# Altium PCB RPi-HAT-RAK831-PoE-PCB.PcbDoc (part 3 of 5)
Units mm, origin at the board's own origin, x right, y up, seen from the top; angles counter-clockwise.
Board outline 65 x 56 mm, 2 copper layers (Top Layer, Bottom Layer); 9 components, 14 nets, 9110 pads, 249 vias.
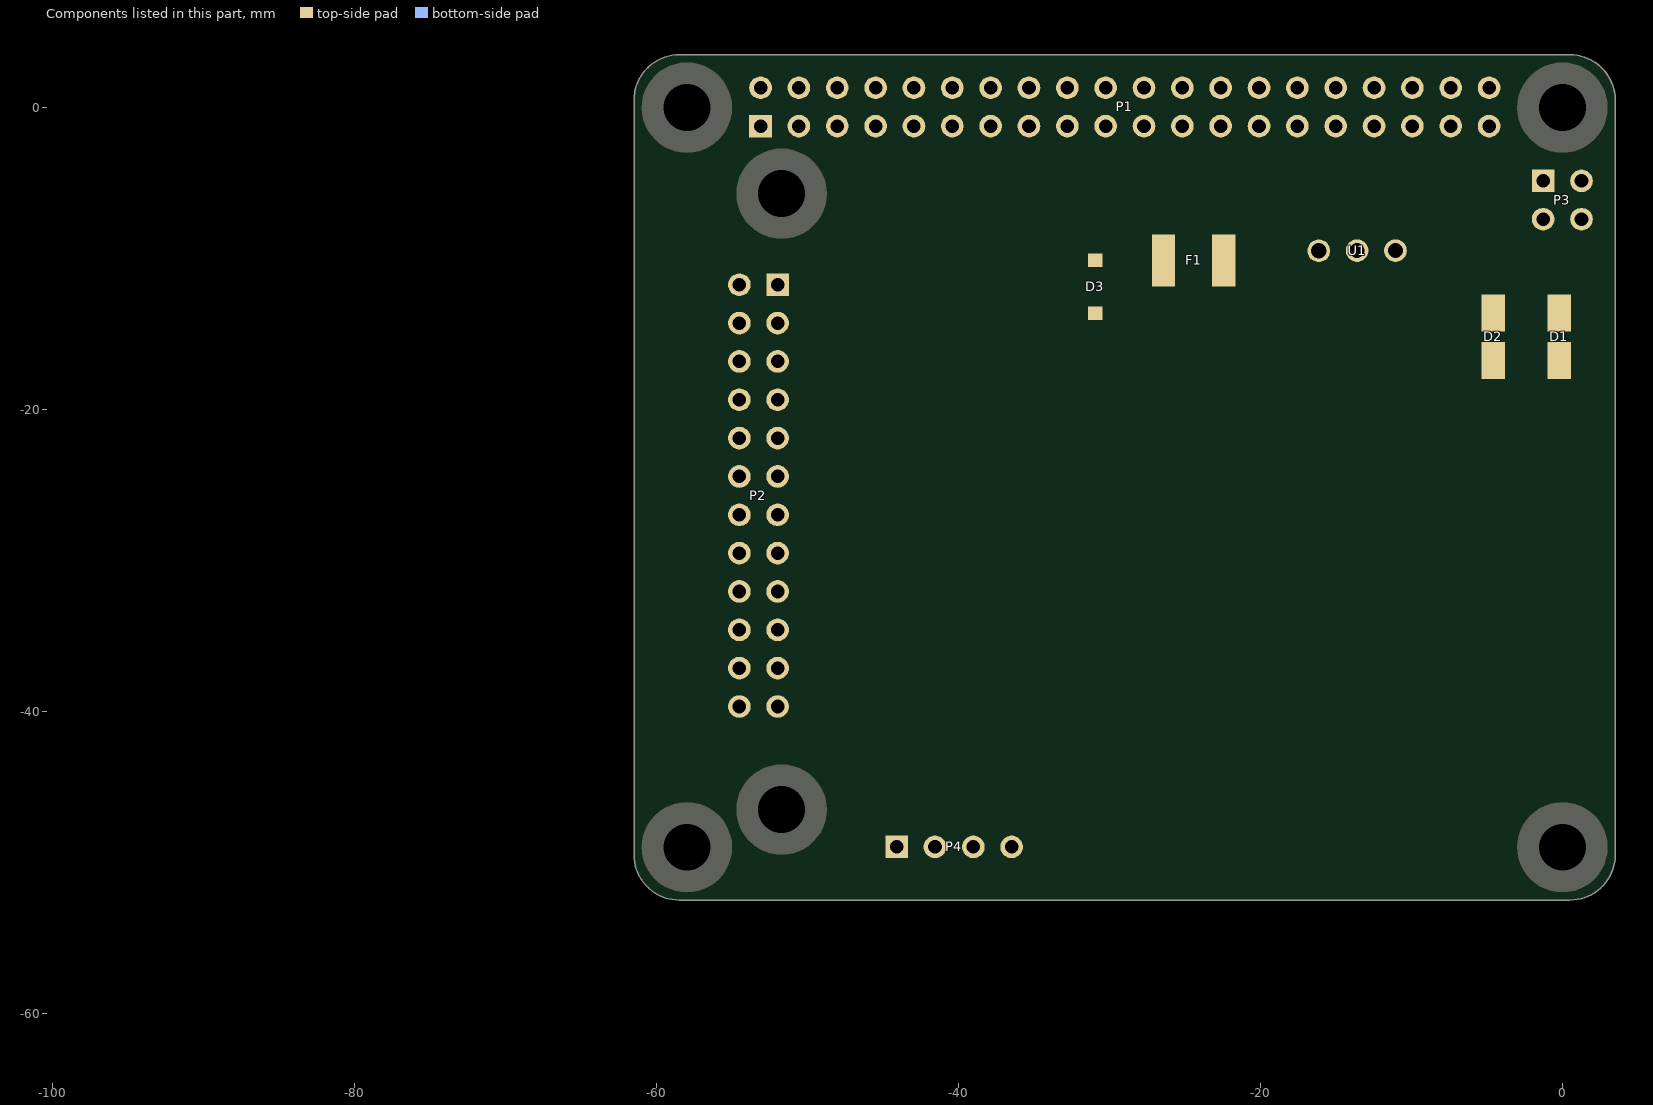
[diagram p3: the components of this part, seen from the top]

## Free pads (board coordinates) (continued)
  round 0.025 on Bottom Overlay: 1(-16.645,-44.787) 1(-16.645,-44.761) 1(-16.645,-44.736) 1(-16.645,-44.71) 1(-16.645,-44.685) 1(-16.645,-44.66) 1(-16.645,-44.634) 1(-16.645,-44.609) 1(-16.645,-44.583) 1(-16.645,-44.558) 1(-16.645,-44.533) 1(-16.645,-44.507) 1(-16.645,-44.482) 1(-16.645,-44.456) 1(-16.62,-45.193) 1(-16.594,-42.043) 1(-16.569,-45.218) 1(-16.493,-45.244) 1(-16.493,-42.729) 1(-16.442,-45.955) 1(-16.34,-45.269) 1(-16.061,-42.729) 1(-15.959,-45.269) 1(-15.959,-42.043) 1(-15.909,-42.755) 1(-15.883,-44.431) 1(-15.883,-44.406) 1(-15.883,-44.38) 1(-15.883,-44.355) 1(-15.883,-44.329) 1(-15.883,-44.304) 1(-15.883,-44.279) 1(-15.883,-44.253) 1(-15.883,-44.228) 1(-15.883,-44.202) 1(-15.883,-44.177) 1(-15.883,-44.152) 1(-15.883,-44.126) 1(-15.883,-44.101) 1(-15.883,-44.075) 1(-15.883,-44.05) 1(-15.883,-44.025) 1(-15.883,-43.999) 1(-15.883,-43.974) 1(-15.883,-43.948) 1(-15.883,-43.923) 1(-15.883,-43.898) 1(-15.883,-43.872) 1(-15.883,-43.847) 1(-15.883,-43.821) 1(-15.883,-43.796) 1(-15.883,-43.771) 1(-15.832,-45.244) 1(-15.832,-42.78) 1(-15.807,-45.955) 1(-15.756,-45.218) 1(-15.756,-42.805) 1(-15.756,-42.069) 1(-15.705,-42.831) 1(-15.68,-45.193) 1(-15.655,-42.856) 1(-15.629,-45.93) 1(-15.629,-45.168) 1(-15.629,-42.094) 1(-15.604,-42.882) 1(-15.578,-45.142) 1(-15.553,-42.907) 1(-15.528,-45.117) 1(-15.528,-42.932) 1(-15.528,-42.12) 1(-15.502,-45.904) 1(-15.477,-45.091) 1(-15.477,-42.958) 1(-15.451,-45.066) 1(-15.451,-42.983) 1(-15.451,-42.145) 1(-15.426,-45.041) 1(-15.426,-43.009) 1(-15.401,-45.879) 1(-15.401,-45.015) 1(-15.401,-43.034) 1(-15.375,-44.99) 1(-15.375,-43.059) 1(-15.375,-42.17) 1(-15.35,-44.964) 1(-15.35,-43.085) 1(-15.324,-44.939) 1(-15.324,-43.11) 1(-15.299,-45.853) 1(-15.299,-44.914) 1(-15.299,-43.136) 1(-15.299,-42.196) 1(-15.274,-44.888) 1(-15.274,-43.161) 1(-15.248,-45.828) 1(-15.248,-44.863) 1(-15.248,-43.212) 1(-15.248,-43.186) 1(-15.248,-42.221) 1(-15.223,-44.837) 1(-15.223,-44.812) 1(-15.223,-43.237) 1(-15.197,-44.787) 1(-15.197,-43.288) 1(-15.197,-43.263) 1(-15.197,-42.247) 1(-15.172,-45.803) 1(-15.172,-44.761) 1(-15.172,-44.736) 1(-15.172,-43.339) 1(-15.172,-43.313) 1(-15.147,-44.71) 1(-15.147,-44.685) 1(-15.147,-43.39) 1(-15.147,-43.364) 1(-15.147,-42.272) 1(-15.121,-45.777) 1(-15.121,-44.66) 1(-15.121,-44.634) 1(-15.121,-44.609) 1(-15.121,-43.44) 1(-15.121,-43.415) 1(-15.096,-44.583) 1(-15.096,-44.558) 1(-15.096,-43.517) 1(-15.096,-43.491) 1(-15.096,-43.466) 1(-15.096,-42.297) 1(-15.07,-45.752) 1(-15.07,-44.533) 1(-15.07,-44.507) 1(-15.07,-44.482) 1(-15.07,-44.456) 1(-15.07,-43.593) 1(-15.07,-43.567) 1(-15.07,-43.542) 1(-15.045,-44.431) 1(-15.045,-44.406) 1(-15.045,-44.38) 1(-15.045,-44.355) 1(-15.045,-44.329) 1(-15.045,-43.72) 1(-15.045,-43.694) 1(-15.045,-43.669) 1(-15.045,-43.644) 1(-15.045,-43.618) 1(-15.045,-42.323) 1(-15.02,-45.726) 1(-15.02,-44.304) 1(-15.02,-44.279) 1(-15.02,-44.253) 1(-15.02,-44.228) 1(-15.02,-44.202) 1(-15.02,-44.177) 1(-15.02,-44.152) 1(-15.02,-44.126) 1(-15.02,-44.101) 1(-15.02,-44.075) 1(-15.02,-44.05) 1(-15.02,-44.025) 1(-15.02,-43.999) 1(-15.02,-43.974) 1(-15.02,-43.948) 1(-15.02,-43.923) 1(-15.02,-43.898) 1(-15.02,-43.872) 1(-15.02,-43.847) 1(-15.02,-43.821) 1(-15.02,-43.796) 1(-15.02,-43.771) 1(-15.02,-43.745) 1(-15.02,-42.348) 1(-14.969,-45.701) 1(-14.969,-42.374) 1(-14.943,-42.399) 1(-14.918,-45.676) 1(-14.893,-45.65) 1(-14.893,-42.424) 1(-14.867,-42.45) 1(-14.842,-45.625) 1(-14.842,-42.475) 1(-14.816,-45.599) 1(-14.791,-42.501) 1(-14.766,-45.574) 1(-14.766,-42.526) 1(-14.74,-45.549) 1(-14.74,-42.551) 1(-14.715,-45.523) 1(-14.715,-42.577) 1(-14.689,-45.498) 1(-14.689,-42.602) 1(-14.664,-45.472) 1(-14.664,-42.628) 1(-14.639,-45.447) 1(-14.639,-42.653) 1(-14.613,-45.422) 1(-14.613,-42.678) 1(-14.588,-45.396) 1(-14.588,-42.704) 1(-14.562,-45.371) 1(-14.562,-42.729) 1(-14.537,-45.345) 1(-14.537,-42.78) 1(-14.537,-42.755) 1(-14.512,-45.32) 1(-14.512,-42.805) 1(-14.486,-45.295) 1(-14.486,-45.269) 1(-14.486,-42.831) 1(-14.461,-45.244) 1(-14.461,-42.882) 1(-14.461,-42.856) 1(-14.435,-45.218) 1(-14.435,-42.907) 1(-14.41,-45.193) 1(-14.41,-45.168) 1(-14.41,-42.958) 1(-14.41,-42.932) 1(-14.385,-45.142) 1(-14.385,-45.117) 1(-14.385,-42.983) 1(-14.359,-45.091) 1(-14.359,-43.034) 1(-14.359,-43.009) 1(-14.334,-45.066) 1(-14.334,-45.041) 1(-14.334,-43.085) 1(-14.334,-43.059) 1(-14.308,-45.015) 1(-14.308,-44.99) 1(-14.308,-43.136) 1(-14.308,-43.11) 1(-14.283,-44.964) 1(-14.283,-44.939) 1(-14.283,-43.186) 1(-14.283,-43.161) 1(-14.258,-44.914) 1(-14.258,-44.888) 1(-14.258,-44.863) 1(-14.258,-43.263) 1(-14.258,-43.237) 1(-14.258,-43.212) 1(-14.232,-44.837) 1(-14.232,-44.812) 1(-14.232,-44.787) 1(-14.232,-43.339) 1(-14.232,-43.313) 1(-14.232,-43.288) 1(-14.207,-44.761) 1(-14.207,-44.736) 1(-14.207,-44.71) 1(-14.207,-43.415) 1(-14.207,-43.39) 1(-14.207,-43.364) 1(-14.181,-44.685) 1(-14.181,-44.66) 1(-14.181,-44.634) 1(-14.181,-44.609) 1(-14.181,-43.517) 1(-14.181,-43.491) 1(-14.181,-43.466) 1(-14.181,-43.44) 1(-14.156,-44.583) 1(-14.156,-44.558) 1(-14.156,-44.533) 1(-14.156,-44.507) 1(-14.156,-44.482) 1(-14.156,-43.644) 1(-14.156,-43.618) 1(-14.156,-43.593) 1(-14.156,-43.567) 1(-14.156,-43.542) 1(-14.131,-44.456) 1(-14.131,-44.431) 1(-14.131,-44.406) 1(-14.131,-44.38) 1(-14.131,-44.355) 1(-14.131,-44.329) 1(-14.131,-44.304) 1(-14.131,-44.279) 1(-14.131,-44.253) 1(-14.131,-43.872) 1(-14.131,-43.847) 1(-14.131,-43.821) 1(-14.131,-43.796) 1(-14.131,-43.771) 1(-14.131,-43.745) 1(-14.131,-43.72) 1(-14.131,-43.694) 1(-14.131,-43.669) 1(-14.105,-44.228) 1(-14.105,-44.202) 1(-14.105,-44.177) 1(-14.105,-44.152) 1(-14.105,-44.126) 1(-14.105,-44.101) 1(-14.105,-44.075) 1(-14.105,-44.05) 1(-14.105,-44.025) 1(-14.105,-43.999) 1(-14.105,-43.974) 1(-14.105,-43.948) 1(-14.105,-43.923) 1(-14.105,-43.898) 1(-13.271,-43.362) 1(-13.271,-43.337) 1(-13.271,-43.311) 1(-13.271,-43.286) 1(-13.271,-43.26) 1(-13.271,-43.235) 1(-13.271,-43.21) 1(-13.271,-43.184) 1(-13.271,-43.159) 1(-13.271,-43.133) 1(-13.271,-43.108) 1(-13.271,-43.083) 1(-13.271,-43.057) 1(-13.22,-43.362) 1(-13.22,-43.337) 1(-13.22,-43.311) 1(-13.22,-43.286) 1(-13.22,-43.26) 1(-13.22,-43.235) 1(-13.22,-43.21) 1(-13.22,-43.057) 1(-13.195,-43.286) 1(-13.195,-43.26) 1(-13.195,-43.235) 1(-13.195,-43.21) 1(-13.195,-43.133) 1(-13.195,-43.108) 1(-13.195,-43.083) 1(-13.17,-43.337) 1(-13.17,-43.311) 1(-13.17,-43.184) 1(-13.17,-43.159) 1(-13.144,-43.362) 1(-13.144,-43.26) 1(-13.144,-43.235) 1(-13.144,-43.21) 1(-13.119,-43.26) 1(-13.119,-43.235) 1(-13.093,-43.362) 1(-13.093,-43.337) 1(-13.093,-43.21) 1(-13.093,-43.184) 1(-13.068,-43.311) 1(-13.068,-43.286) 1(-13.068,-43.26) 1(-13.068,-43.159) 1(-13.068,-43.133) 1(-13.068,-43.108) 1(-13.043,-43.235) 1(-13.043,-43.21) 1(-13.043,-43.184) 1(-13.043,-43.083) 1(-13.043,-43.057) 1(-13.017,-43.362) 1(-13.017,-43.337) 1(-13.017,-43.311) 1(-13.017,-43.286) 1(-13.017,-43.26) 1(-13.017,-43.235) 1(-13.017,-43.21) 1(-13.017,-43.184) 1(-12.966,-43.362) 1(-12.966,-43.337) 1(-12.966,-43.311) 1(-12.966,-43.286) 1(-12.966,-43.26) 1(-12.966,-43.235) 1(-12.966,-43.21) 1(-12.966,-43.184) 1(-12.966,-43.159) 1(-12.966,-43.133) 1(-12.966,-43.108) 1(-12.966,-43.083) 1(-12.966,-43.057) 1(-12.941,-43.083) 1(-12.941,-43.057) 1(-12.839,-43.362) 1(-12.839,-43.337) 1(-12.839,-43.311) 1(-12.839,-43.286) 1(-12.839,-43.26) 1(-12.839,-43.235) 1(-12.839,-43.21) 1(-12.839,-43.184) 1(-12.839,-43.159) 1(-12.839,-43.133) 1(-12.839,-43.108) 1(-12.763,-44.886) 1(-12.763,-43.362) 1(-12.763,-43.337) 1(-12.763,-43.311) 1(-12.763,-43.286) 1(-12.763,-43.26) 1(-12.763,-43.235) 1(-12.763,-43.21) 1(-12.763,-43.184) 1(-12.763,-43.159) 1(-12.763,-43.133) 1(-12.763,-43.108) 1(-12.738,-44.861) 1(-12.738,-44.835) 1(-12.738,-44.81) 1(-12.738,-44.784) 1(-12.738,-44.759) 1(-12.738,-44.734) 1(-12.738,-44.708) 1(-12.712,-44.683) 1(-12.712,-44.657) 1(-12.712,-44.632) 1(-12.712,-44.607) 1(-12.712,-44.581) 1(-12.712,-44.556) 1(-12.712,-44.53) 1(-12.712,-44.505) 1(-12.712,-44.48) 1(-12.712,-44.454) 1(-12.712,-44.429) 1(-12.712,-44.403) 1(-12.712,-44.378) 1(-12.712,-44.353) 1(-12.712,-44.327) 1(-12.712,-44.302) 1(-12.712,-44.276) 1(-12.712,-44.251) 1(-12.712,-44.226) 1(-12.712,-44.2) 1(-12.712,-44.175) 1(-12.712,-44.149) 1(-12.712,-44.124) 1(-12.712,-44.099) 1(-12.712,-44.073) 1(-12.712,-44.048) 1(-12.712,-44.022) 1(-12.712,-43.997) 1(-12.712,-43.972) 1(-12.712,-43.946) 1(-12.712,-43.921) 1(-12.712,-43.895) 1(-12.712,-43.87) 1(-12.712,-43.845) 1(-12.712,-43.819) 1(-12.712,-43.794) 1(-12.712,-43.768) 1(-12.712,-43.743) 1(-12.712,-43.718) 1(-12.712,-43.692) 1(-12.712,-43.667) 1(-12.712,-43.641) 1(-12.712,-43.616) 1(-12.712,-43.591) 1(-12.712,-43.565) 1(-12.712,-43.54) 1(-12.712,-43.514) 1(-12.712,-43.489) 1(-12.712,-43.464) 1(-12.687,-43.438) 1(-12.687,-43.413) 1(-12.687,-43.387) 1(-12.687,-43.083) 1(-12.687,-43.057) 1(-12.662,-43.362) 1(-12.662,-43.337) 1(-12.636,-43.311) 1(-12.636,-43.286) 1(-12.611,-43.26) 1(-12.585,-43.235) 1(-12.535,-43.21) 1(-12.509,-43.184) 1(-12.458,-43.159) 1(-12.382,-43.133) 1(-12.306,-43.108) 1(-12.255,-44.886) 1(-12.255,-44.861) 1(-12.255,-44.835) 1(-12.255,-44.81) 1(-12.23,-44.784) 1(-12.23,-44.759) 1(-12.204,-44.759) 1(-12.204,-44.251) 1(-12.204,-44.226) 1(-12.204,-44.2) 1(-12.204,-44.175) 1(-12.204,-44.149) 1(-12.204,-44.124) 1(-12.204,-44.099) 1(-12.204,-44.073) 1(-12.204,-43.718) 1(-12.204,-43.692) 1(-12.204,-43.667) 1(-12.204,-43.641) 1(-12.204,-43.616) 1(-12.204,-43.591) 1(-12.204,-43.565) 1(-12.204,-43.54) 1(-12.179,-44.784) 1(-12.179,-44.327) 1(-12.179,-44.302) 1(-12.179,-44.276) 1(-12.179,-43.514) 1(-12.179,-43.489) 1(-12.179,-43.083) 1(-12.154,-44.81) 1(-12.154,-44.403) 1(-12.154,-44.378) 1(-12.154,-44.353) 1(-12.154,-43.464) 1(-12.128,-44.835) 1(-12.128,-44.429) 1(-12.128,-44.073) 1(-12.103,-44.454) 1(-12.103,-43.743) 1(-12.103,-43.438) 1(-12.077,-44.861) 1(-12.077,-44.48) 1(-12.052,-44.505) 1(-12.027,-44.886) 1(-12.027,-44.099) 1(-12.027,-43.413) 1(-11.976,-44.53) 1(-11.95,-44.911) 1(-11.925,-44.124) 1(-11.9,-43.768) 1(-11.9,-43.413) 1(-11.849,-44.937) 1(-11.849,-44.149) 1(-11.823,-43.438) 1(-11.798,-43.464) 1(-11.773,-44.175) 1(-11.773,-43.794) 1(-11.747,-43.514) 1(-11.747,-43.489) 1(-11.722,-44.53) 1(-11.722,-44.2) 1(-11.722,-43.591) 1(-11.722,-43.565) 1(-11.722,-43.54) 1(-11.722,-43.083) 1(-11.696,-44.226) 1(-11.696,-43.819) 1(-11.696,-43.641) 1(-11.696,-43.616) 1(-11.671,-44.505) 1(-11.671,-44.48) 1(-11.671,-44.251) 1(-11.646,-44.454) 1(-11.646,-44.302) 1(-11.646,-44.276) 1(-11.62,-44.429) 1(-11.62,-44.403) 1(-11.62,-44.378) 1(-11.62,-44.353) 1(-11.62,-44.327) 1(-11.595,-43.108) 1(-11.569,-43.845) 1(-11.544,-44.937) 1(-11.519,-43.87) 1(-11.519,-43.133) 1(-11.468,-43.895) 1(-11.468,-43.159) 1(-11.442,-44.911) 1(-11.417,-43.184) 1(-11.392,-44.886) 1(-11.392,-43.921) 1(-11.392,-43.21) 1(-11.366,-43.946) 1(-11.341,-44.861) 1(-11.341,-43.235) 1(-11.315,-43.972) 1(-11.315,-43.286) 1(-11.315,-43.26) 1(-11.29,-44.835) 1(-11.29,-43.997) 1(-11.29,-43.311) 1(-11.265,-44.81) 1(-11.265,-44.022) 1(-11.265,-43.337) 1(-11.239,-44.784) 1(-11.239,-44.048) 1(-11.239,-43.413) 1(-11.239,-43.387) 1(-11.239,-43.362) 1(-11.214,-44.759) 1(-11.214,-44.073) 1(-11.214,-43.489) 1(-11.214,-43.464) 1(-11.214,-43.438) 1(-11.188,-44.734) 1(-11.188,-44.708) 1(-11.188,-44.124) 1(-11.188,-44.099) 1(-11.188,-43.641) 1(-11.188,-43.616) 1(-11.188,-43.591) 1(-11.188,-43.565) 1(-11.188,-43.54) 1(-11.188,-43.514) 1(-11.163,-44.683) 1(-11.163,-44.657) 1(-11.163,-44.175) 1(-11.163,-44.149) 1(-11.138,-44.632) 1(-11.138,-44.607) 1(-11.138,-44.581) 1(-11.138,-44.251) 1(-11.138,-44.226) 1(-11.138,-44.2) 1(-11.112,-44.556) 1(-11.112,-44.53) 1(-11.112,-44.505) 1(-11.112,-44.48) 1(-11.112,-44.454) 1(-11.112,-44.429) 1(-11.112,-44.403) 1(-11.112,-44.378) 1(-11.112,-44.353) 1(-11.112,-44.327) 1(-11.112,-44.302) 1(-11.112,-44.276) 1(-10.934,-44.886) 1(-10.909,-44.861) 1(-10.909,-44.835) 1(-10.884,-44.81) 1(-10.884,-44.784) 1(-10.884,-43.438) 1(-10.884,-43.413) 1(-10.884,-43.387) 1(-10.884,-43.362) 1(-10.884,-43.337) 1(-10.884,-43.311) 1(-10.884,-43.286) 1(-10.884,-43.26) 1(-10.884,-43.235) 1(-10.884,-43.21) 1(-10.884,-43.184) 1(-10.884,-43.159) 1(-10.884,-43.133) 1(-10.858,-44.759) 1(-10.858,-44.734) 1(-10.858,-43.514) 1(-10.858,-43.489) 1(-10.858,-43.464) 1(-10.858,-43.108) 1(-10.858,-43.083) 1(-10.858,-43.057) 1(-10.858,-43.032) 1(-10.833,-44.708) 1(-10.833,-44.683) 1(-10.833,-43.591) 1(-10.833,-43.565) 1(-10.833,-43.54) 1(-10.833,-43.006) 1(-10.833,-42.981) 1(-10.833,-42.956) 1(-10.833,-42.93) 1(-10.807,-44.657) 1(-10.807,-43.641) 1(-10.807,-43.616) 1(-10.807,-42.905) 1(-10.782,-44.632) 1(-10.782,-44.607) 1(-10.782,-43.667) 1(-10.782,-42.879) 1(-10.782,-42.854) 1(-10.757,-44.581) 1(-10.757,-44.556) 1(-10.757,-43.718) 1(-10.757,-43.692) 1(-10.757,-42.829) 1(-10.757,-42.803) 1(-10.731,-44.53) 1(-10.731,-43.743) 1(-10.731,-42.778) 1(-10.706,-44.505) 1(-10.706,-44.48) 1(-10.706,-43.768) 1(-10.706,-42.752) 1(-10.68,-44.454) 1(-10.68,-44.429) 1(-10.68,-43.794) 1(-10.68,-42.727) 1(-10.655,-44.403) 1(-10.655,-44.378) 1(-10.655,-43.819) 1(-10.655,-42.702) 1(-10.63,-44.353) 1(-10.63,-43.845) 1(-10.604,-44.327) 1(-10.604,-44.302) 1(-10.604,-42.676) 1(-10.579,-44.276) 1(-10.579,-44.251) 1(-10.579,-43.87) 1(-10.579,-42.651) 1(-10.553,-44.226) 1(-10.553,-44.2) 1(-10.528,-44.175) 1(-10.528,-44.149) 1(-10.528,-43.895) 1(-10.528,-42.625) 1(-10.503,-44.124) 1(-10.503,-43.921) 1(-10.477,-44.099) 1(-10.477,-44.073) 1(-10.477,-42.6) 1(-10.452,-44.048) 1(-10.452,-44.022) 1(-10.426,-43.997) 1(-10.426,-43.972) 1(-10.426,-43.946) 1(-10.426,-42.575) 1(-10.325,-42.549) 1(-10.274,-43.387) 1(-10.274,-43.362) 1(-10.274,-43.337) 1(-10.274,-43.311) 1(-10.274,-43.286) 1(-10.274,-43.26) 1(-10.274,-43.235) 1(-10.274,-43.21) 1(-10.274,-43.184) 1(-10.249,-44.886) 1(-10.249,-44.861) 1(-10.249,-43.464) 1(-10.249,-43.438) 1(-10.249,-43.413) 1(-10.249,-43.159) 1(-10.249,-43.133) 1(-10.249,-43.108) 1(-10.223,-44.835) 1(-10.223,-44.81) 1(-10.223,-43.489) 1(-10.223,-43.083) 1(-10.198,-44.784) 1(-10.198,-43.514) 1(-10.198,-43.057) 1(-10.172,-44.759) 1(-10.172,-44.734) 1(-10.172,-43.54) 1(-10.172,-43.032) 1(-10.147,-44.708) 1(-10.147,-44.683) 1(-10.122,-44.657) 1(-10.122,-44.632) 1(-10.122,-43.565) 1(-10.122,-43.006) 1(-10.096,-44.607) 1(-10.096,-44.581) 1(-10.071,-44.556) 1(-10.071,-43.591) 1(-10.045,-44.53) 1(-10.045,-44.505) 1(-10.045,-42.524) 1(-10.02,-44.48) 1(-10.02,-44.454) 1(-10.02,-42.981) 1(-9.995,-44.429) 1(-9.995,-44.403) 1(-9.969,-44.378) 1(-9.969,-44.353) 1(-9.944,-44.327) 1(-9.944,-44.302) 1(-9.918,-44.276) 1(-9.918,-44.251) 1(-9.893,-44.226) 1(-9.868,-44.2) 1(-9.868,-44.175) 1(-9.842,-44.149) 1(-9.842,-44.124) 1(-9.817,-44.099) 1(-9.791,-44.073) 1(-9.436,-44.886) 1(-9.436,-44.861) 1(-9.436,-44.835) 1(-9.436,-44.81) 1(-9.436,-44.784) 1(-9.436,-44.759) 1(-9.436,-44.734) 1(-9.436,-44.708) 1(-9.436,-44.683) 1(-9.436,-44.657) 1(-9.436,-44.632) 1(-9.436,-44.607) 1(-9.436,-44.581) 1(-9.436,-44.556) 1(-9.436,-44.53) 1(-9.436,-44.505) 1(-9.436,-44.48) 1(-9.436,-44.454) 1(-9.436,-44.429) 1(-9.436,-44.403) 1(-9.436,-44.378) 1(-9.436,-44.353) 1(-9.436,-44.327) 1(-9.436,-44.302) 1(-9.436,-44.276) 1(-9.436,-44.251) 1(-9.436,-44.226) 1(-9.436,-44.2) 1(-9.436,-44.175) 1(-9.436,-44.149) 1(-9.436,-44.124) 1(-9.436,-44.099) 1(-9.436,-44.073) 1(-9.436,-43.591) 1(-9.436,-43.565) 1(-9.436,-43.54) 1(-9.436,-43.514) 1(-9.436,-43.489) 1(-9.436,-43.464) 1(-9.436,-43.438) 1(-9.436,-43.413) 1(-9.436,-43.387) 1(-9.436,-43.362) 1(-9.436,-43.337) 1(-9.436,-43.311) 1(-9.436,-43.286) 1(-9.436,-43.26) 1(-9.436,-43.235) 1(-9.436,-43.21) 1(-9.436,-43.184) 1(-9.436,-43.159) 1(-9.436,-43.133) 1(-9.436,-43.108) 1(-9.436,-43.083) 1(-9.436,-43.057) 1(-9.436,-43.032) 1(-9.436,-43.006) 1(-9.436,-42.981) 1(-8.979,-46.181) 1(-8.979,-46.156) 1(-8.979,-41.889) 1(-8.979,-41.863) 1(-8.953,-46.131) 1(-8.953,-41.94) 1(-8.953,-41.914) 1(-8.928,-46.207) 1(-8.928,-46.105) 1(-8.928,-46.08) 1(-8.928,-41.965) 1(-8.928,-41.838) 1(-8.902,-46.054) 1(-8.902,-42.016) 1(-8.902,-41.99) 1(-8.877,-46.232) 1(-8.877,-46.029) 1(-8.877,-46.004) 1(-8.877,-42.041) 1(-8.877,-41.813) 1(-8.852,-46.258) 1(-8.852,-45.978) 1(-8.852,-42.067) 1(-8.852,-41.787) 1(-8.826,-45.953) 1(-8.826,-45.927) 1(-8.826,-44.886) 1(-8.826,-44.861) 1(-8.826,-44.835) 1(-8.826,-44.81) 1(-8.826,-44.784) 1(-8.826,-44.759) 1(-8.826,-44.734) 1(-8.826,-44.708) 1(-8.826,-44.683) 1(-8.826,-44.657) 1(-8.826,-44.632) 1(-8.826,-44.607) 1(-8.826,-44.581) 1(-8.826,-44.556) 1(-8.826,-44.53) 1(-8.826,-44.505) 1(-8.826,-44.48) 1(-8.826,-44.454) 1(-8.826,-44.429) 1(-8.826,-44.403) 1(-8.826,-44.378) 1(-8.826,-44.353) 1(-8.826,-44.327) 1(-8.826,-44.302) 1(-8.826,-44.276) 1(-8.826,-44.251) 1(-8.826,-44.226) 1(-8.826,-44.2) 1(-8.826,-44.175) 1(-8.826,-44.149) 1(-8.826,-44.124) 1(-8.826,-44.099) 1(-8.826,-44.073) 1(-8.826,-44.048) 1(-8.826,-44.022) 1(-8.826,-43.997) 1(-8.826,-43.972) 1(-8.826,-43.946) 1(-8.826,-43.921) 1(-8.826,-43.895) 1(-8.826,-43.87) 1(-8.826,-43.845) 1(-8.826,-43.819) 1(-8.826,-43.794) 1(-8.826,-43.768) 1(-8.826,-43.743) 1(-8.826,-43.718) 1(-8.826,-43.692) 1(-8.826,-43.667) 1(-8.826,-43.641) 1(-8.826,-43.616) 1(-8.826,-43.591) 1(-8.826,-43.565) 1(-8.826,-43.54) 1(-8.826,-43.514) 1(-8.826,-43.489) 1(-8.826,-43.464) 1(-8.826,-43.438) 1(-8.826,-43.413) 1(-8.826,-43.387) 1(-8.826,-43.362) 1(-8.826,-43.337) 1(-8.826,-43.311) 1(-8.826,-43.286) 1(-8.826,-43.26) 1(-8.826,-43.235) 1(-8.826,-43.21) 1(-8.826,-43.184) 1(-8.826,-43.159) 1(-8.826,-43.133) 1(-8.826,-43.108) 1(-8.826,-43.083) 1(-8.826,-43.057) 1(-8.826,-43.032) 1(-8.826,-43.006) 1(-8.826,-42.981) 1(-8.826,-42.956) 1(-8.826,-42.93) 1(-8.826,-42.905) 1(-8.826,-42.879) 1(-8.826,-42.854) 1(-8.826,-42.829) 1(-8.826,-42.803) 1(-8.826,-42.778) 1(-8.826,-42.752) 1(-8.826,-42.727) 1(-8.826,-42.702) 1(-8.826,-42.676) 1(-8.826,-42.651) 1(-8.826,-42.625) 1(-8.826,-42.6) 1(-8.826,-42.575) 1(-8.826,-42.549) 1(-8.826,-42.524) 1(-8.826,-42.117) 1(-8.826,-42.092) 1(-8.801,-46.283) 1(-8.801,-45.927) 1(-8.801,-42.117) 1(-8.801,-41.762) 1(-8.775,-45.953) 1(-8.75,-46.308) 1(-8.75,-42.092) 1(-8.75,-41.736) 1(-8.725,-45.978) 1(-8.725,-42.067) 1(-8.699,-46.334) 1(-8.699,-41.711) 1(-8.674,-46.004) 1(-8.674,-42.041) 1(-8.648,-46.359) 1(-8.648,-45.724) 1(-8.648,-45.699) 1(-8.648,-45.673) 1(-8.648,-42.346) 1(-8.648,-41.686) 1(-8.623,-46.029) 1(-8.623,-45.648) 1(-8.623,-42.397) 1(-8.623,-42.371) 1(-8.623,-42.321) 1(-8.623,-42.016) 1(-8.598,-46.385) 1(-8.598,-45.75) 1(-8.598,-45.623) 1(-8.598,-45.597) 1(-8.598,-42.422) 1(-8.598,-42.295) 1(-8.598,-41.66) 1(-8.572,-46.054) 1(-8.572,-45.572) 1(-8.572,-42.473) 1(-8.572,-42.448) 1(-8.572,-41.99) 1(-8.547,-46.41) 1(-8.547,-45.775) 1(-8.547,-45.546) 1(-8.547,-45.521) 1(-8.547,-42.498) 1(-8.547,-42.27) 1(-8.547,-41.635) 1(-8.521,-46.08) 1(-8.521,-42.524) 1(-8.521,-42.244) 1(-8.521,-41.965) 1(-8.496,-45.8) 1(-8.496,-45.521) 1(-8.496,-44.175) 1(-8.496,-44.149) 1(-8.496,-44.124) 1(-8.496,-44.099) 1(-8.496,-44.073) 1(-8.496,-44.048) 1(-8.496,-44.022) 1(-8.496,-43.997) 1(-8.496,-43.972) 1(-8.496,-43.946) 1(-8.496,-43.921) 1(-8.496,-43.895) 1(-8.496,-43.87) 1(-8.496,-43.845) 1(-8.496,-42.524) 1(-8.471,-46.435) 1(-8.471,-46.105) 1(-8.471,-45.826) 1(-8.471,-44.327) 1(-8.471,-44.302) 1(-8.471,-44.276) 1(-8.471,-44.251) 1(-8.471,-44.226) 1(-8.471,-44.2) 1(-8.471,-43.819) 1(-8.471,-43.794) 1(-8.471,-43.768) 1(-8.471,-43.743) 1(-8.471,-43.718) 1(-8.471,-43.692) 1(-8.471,-41.94) 1(-8.471,-41.609) 1(-8.445,-45.546) 1(-8.445,-44.403) 1(-8.445,-44.378) 1(-8.445,-44.353) 1(-8.445,-43.667) 1(-8.445,-43.641) 1(-8.445,-43.616) 1(-8.445,-42.498) 1(-8.445,-42.219) 1(-8.42,-45.572) 1(-8.42,-44.454) 1(-8.42,-44.429) 1(-8.42,-43.591) 1(-8.42,-43.565) 1(-8.42,-41.914) 1(-8.42,-41.584) 1(-8.394,-46.461) 1(-8.394,-46.131) 1(-8.394,-45.851) 1(-8.394,-44.505) 1(-8.394,-44.48) 1(-8.394,-43.54) 1(-8.394,-43.514) 1(-8.394,-42.473) 1(-8.394,-42.194) 1(-8.369,-44.556) 1(-8.369,-44.53) 1(-8.369,-43.489) 1(-8.369,-43.464) 1(-8.369,-42.448) 1(-8.369,-42.168) 1(-8.344,-46.156) 1(-8.344,-45.877) 1(-8.344,-45.597) 1(-8.344,-45.267) 1(-8.344,-45.242) 1(-8.344,-44.581) 1(-8.344,-43.438) 1(-8.344,-41.889) 1(-8.344,-41.559) 1(-8.318,-46.486) 1(-8.318,-45.623) 1(-8.318,-45.216) 1(-8.318,-44.607) 1(-8.318,-43.413) 1(-8.318,-43.387) 1(-8.318,-42.829) 1(-8.318,-42.803) 1(-8.318,-42.778) 1(-8.318,-42.422) 1(-8.293,-45.902) 1(-8.293,-45.292) 1(-8.293,-45.191) 1(-8.293,-45.165) 1(-8.293,-44.657) 1(-8.293,-44.632) 1(-8.293,-42.854) 1(-8.293,-42.752) 1(-8.293,-42.143) 1(-8.267,-46.181) 1(-8.267,-45.648) 1(-8.267,-45.14) 1(-8.267,-44.683) 1(-8.267,-43.362) 1(-8.267,-42.905) 1(-8.267,-42.879) 1(-8.267,-41.863) 1(-8.242,-46.512) 1(-8.242,-45.318) 1(-8.242,-45.115) 1(-8.242,-44.708) 1(-8.242,-43.337) 1(-8.242,-43.311) 1(-8.242,-42.93) 1(-8.242,-42.727) 1(-8.242,-42.397) 1(-8.242,-41.533) 1(-8.217,-45.927) 1(-8.217,-45.115) 1(-8.217,-44.734) 1(-8.217,-42.93) 1(-8.217,-42.117) 1(-8.191,-45.673) 1(-8.191,-45.343) 1(-8.191,-43.286) 1(-8.191,-42.702) 1(-8.191,-42.371) 1(-8.191,-41.838) 1(-8.166,-46.207) 1(-8.166,-45.14) 1(-8.166,-44.759) 1(-8.166,-43.26) 1(-8.166,-42.905) 1(-8.166,-42.092) 1(-8.166,-41.508) 1(-8.14,-45.953) 1(-8.14,-45.369) 1(-8.14,-44.784) 1(-8.14,-43.235) 1(-8.14,-42.879) 1(-8.14,-42.676) 1(-8.14,-42.346) 1(-8.115,-46.537) 1(-8.115,-45.699) 1(-8.115,-45.165) 1(-8.115,-41.813) 1(-8.09,-46.232) 1(-8.09,-45.191) 1(-8.09,-44.81) 1(-8.09,-43.21) 1(-8.09,-42.651) 1(-8.064,-45.394) 1(-8.064,-44.835) 1(-8.064,-42.854) 1(-8.064,-42.067) 1(-8.064,-41.482) 1(-8.039,-45.978) 1(-8.039,-45.724) 1(-8.039,-43.184) 1(-8.039,-42.321) 1(-8.013,-45.419) 1(-8.013,-45.216) 1(-8.013,-44.861) 1(-8.013,-43.159) 1(-8.013,-42.829) 1(-8.013,-42.625) 1(-7.988,-46.562) 1(-7.988,-41.787) 1(-7.963,-46.258) 1(-7.963,-44.175) 1(-7.963,-44.149) 1(-7.963,-44.124) 1(-7.963,-44.099) 1(-7.963,-44.073) 1(-7.963,-44.048) 1(-7.963,-44.022) 1(-7.963,-43.997) 1(-7.963,-43.972) 1(-7.963,-43.946) 1(-7.963,-43.921) 1(-7.963,-43.895) 1(-7.963,-43.87) 1(-7.963,-43.845) 1(-7.963,-42.803) 1(-7.963,-42.295) 1(-7.963,-42.041) 1(-7.937,-45.242) 1(-7.937,-44.886) 1(-7.937,-44.251) 1(-7.937,-44.226) 1(-7.937,-44.2) 1(-7.937,-43.819) 1(-7.937,-43.794) 1(-7.937,-43.768) 1(-7.937,-43.133) 1(-7.937,-42.6) 1(-7.912,-45.75) 1(-7.912,-45.445) 1(-7.912,-44.327) 1(-7.912,-44.302) 1(-7.912,-44.276) 1(-7.912,-43.743) 1(-7.912,-43.718) 1(-7.886,-46.004) 1(-7.886,-44.378) 1(-7.886,-44.353) 1(-7.886,-43.692) 1(-7.886,-43.667) 1(-7.861,-44.911) 1(-7.861,-44.403) 1(-7.861,-43.641) 1(-7.861,-43.108) 1(-7.861,-42.778) 1(-7.861,-42.27) 1(-7.861,-41.762) 1(-7.861,-41.457) 1(-7.836,-45.267) 1(-7.836,-44.429) 1(-7.836,-43.616) 1(-7.836,-42.575) 1(-7.836,-42.016) 1(-7.81,-46.588) 1(-7.81,-44.454) 1(-7.81,-43.591) 1(-7.81,-43.565) 1(-7.759,-45.775) 1(-7.759,-44.48) 1(-7.759,-43.54) 1(-7.759,-42.752) 1(-7.734,-45.47) 1(-7.734,-44.937) 1(-7.734,-44.505) 1(-7.734,-43.083) 1(-7.709,-46.283) 1(-7.709,-43.514) 1(-7.683,-46.029) 1(-7.658,-42.549) 1(-7.607,-44.53) 1(-7.607,-43.489) 1(-7.607,-41.736) 1(-7.582,-45.292) 1(-7.556,-45.292) 1(-7.48,-44.53) 1(-7.48,-43.489) 1(-7.455,-41.736) 1(-7.429,-46.283) 1(-7.429,-46.029) 1(-7.404,-43.514) 1(-7.404,-42.549) 1(-7.378,-45.775) 1(-7.378,-45.47) 1(-7.378,-44.937) 1(-7.378,-44.505) 1(-7.353,-43.54) 1(-7.353,-43.083) 1(-7.328,-46.588) 1(-7.328,-44.48) 1(-7.328,-42.752) 1(-7.302,-44.454) 1(-7.302,-43.565) 1(-7.277,-45.267) 1(-7.277,-44.429) 1(-7.277,-43.591) 1(-7.251,-44.403) 1(-7.251,-43.616) 1(-7.251,-43.108) 1(-7.251,-42.575) 1(-7.226,-46.004) 1(-7.226,-45.75) 1(-7.226,-45.445) 1(-7.226,-44.911) 1(-7.226,-44.378) 1(-7.226,-43.667) 1(-7.226,-43.641) 1(-7.226,-42.016) 1(-7.201,-45.242) 1(-7.201,-44.353) 1(-7.201,-44.327) 1(-7.201,-43.692) 1(-7.201,-42.778) 1(-7.201,-42.27) 1(-7.201,-41.762) 1(-7.201,-41.457) 1(-7.175,-46.258) 1(-7.175,-44.302) 1(-7.175,-44.276) 1(-7.175,-44.251) 1(-7.175,-44.226) 1(-7.175,-43.794) 1(-7.175,-43.768) 1(-7.175,-43.743) 1(-7.175,-43.718) 1(-7.175,-43.133) 1(-7.15,-46.562) 1(-7.15,-44.886) 1(-7.15,-44.2) 1(-7.15,-44.175) 1(-7.15,-44.149) 1(-7.15,-44.124) 1(-7.15,-44.099) 1(-7.15,-43.921) 1(-7.15,-43.895) 1(-7.15,-43.87) 1(-7.15,-43.845) 1(-7.15,-43.819) 1(-7.15,-42.6) 1(-7.124,-45.419) 1(-7.124,-45.216) 1(-7.124,-44.073) 1(-7.124,-44.048) 1(-7.124,-44.022) 1(-7.124,-43.997) 1(-7.124,-43.972) 1(-7.124,-43.946) 1(-7.099,-45.724) 1(-7.099,-44.861) 1(-7.099,-43.159) 1(-7.099,-42.803) 1(-7.099,-42.295) 1(-7.099,-42.041) 1(-7.074,-45.978) 1(-7.074,-45.394) 1(-7.074,-41.787) 1(-7.048,-46.232) 1(-7.048,-45.191) 1(-7.048,-44.835) 1(-7.048,-43.184) 1(-7.048,-42.829) 1(-7.048,-42.625) 1(-7.023,-46.537) 1(-7.023,-45.699) 1(-7.023,-42.321) 1(-6.997,-45.953) 1(-6.997,-45.369) 1(-6.997,-45.165) 1(-6.997,-44.81) 1(-6.997,-43.21) 1(-6.997,-42.854) 1(-6.997,-42.067) 1(-6.997,-41.482) 1(-6.972,-46.207) 1(-6.972,-44.784) 1(-6.972,-43.235) 1(-6.972,-42.651) 1(-6.947,-45.673) 1(-6.947,-45.343) 1(-6.947,-45.14) 1(-6.947,-42.879) 1(-6.947,-42.346) 1(-6.947,-41.813) 1(-6.921,-45.927) 1(-6.921,-44.759) 1(-6.921,-43.26) 1(-6.921,-42.676) 1(-6.896,-46.512) 1(-6.896,-45.318) 1(-6.896,-45.115) 1(-6.896,-44.734) 1(-6.896,-43.286) 1(-6.896,-42.905) 1(-6.896,-42.092) 1(-6.896,-41.508) 1(-6.87,-46.181) 1(-6.87,-45.648) 1(-6.87,-44.708) 1(-6.87,-43.311) 1(-6.87,-42.702) 1(-6.87,-42.371) 1(-6.87,-41.838) 1(-6.845,-45.902) 1(-6.845,-45.115) 1(-6.845,-44.683) 1(-6.845,-43.337) 1(-6.845,-42.905) 1(-6.845,-42.117) 1(-6.82,-46.486) 1(-6.82,-45.623) 1(-6.82,-45.292) 1(-6.82,-45.165) 1(-6.82,-45.14) 1(-6.82,-44.657) 1(-6.82,-43.362) 1(-6.82,-42.879) 1(-6.82,-42.854) 1(-6.82,-42.727) 1(-6.82,-42.397) 1(-6.82,-41.533) 1(-6.794,-46.156) 1(-6.794,-45.877) 1(-6.794,-45.267) 1(-6.794,-45.191) 1(-6.794,-44.632) 1(-6.794,-43.387) 1(-6.794,-42.829) 1(-6.794,-42.752) 1(-6.794,-41.863) 1(-6.769,-45.597) 1(-6.769,-45.242) 1(-6.769,-45.216) 1(-6.769,-44.607) 1(-6.769,-43.438) 1(-6.769,-43.413) 1(-6.769,-42.803) 1(-6.769,-42.778) 1(-6.769,-42.143) 1(-6.743,-46.461) 1(-6.743,-46.131) 1(-6.743,-45.851) 1(-6.743,-44.581) 1(-6.743,-44.556) 1(-6.743,-43.464) 1(-6.743,-42.422) 1(-6.718,-45.572) 1(-6.718,-44.53) 1(-6.718,-44.505) 1(-6.718,-43.514) 1(-6.718,-43.489) 1(-6.718,-42.448) 1(-6.718,-42.168) 1(-6.718,-41.889) 1(-6.718,-41.559) 1(-6.693,-44.48) 1(-6.693,-44.454) 1(-6.693,-43.565) 1(-6.693,-43.54) 1(-6.667,-46.435) 1(-6.667,-46.105) 1(-6.667,-45.826) 1(-6.667,-45.546) 1(-6.667,-44.429) 1(-6.667,-44.403) 1(-6.667,-44.378) 1(-6.667,-43.641) 1(-6.667,-43.616) 1(-6.667,-43.591) 1(-6.667,-42.473) 1(-6.667,-42.194) 1(-6.667,-41.584) 1(-6.642,-45.521) 1(-6.642,-44.353) 1(-6.642,-44.327) 1(-6.642,-44.302) 1(-6.642,-43.743) 1(-6.642,-43.718) 1(-6.642,-43.692) 1(-6.642,-43.667) 1(-6.642,-41.914) 1(-6.616,-46.08) 1(-6.616,-45.8) 1(-6.616,-44.276) 1(-6.616,-44.251) 1(-6.616,-44.226) 1(-6.616,-44.2) 1(-6.616,-44.175) 1(-6.616,-44.149) 1(-6.616,-44.124) 1(-6.616,-43.895) 1(-6.616,-43.87) 1(-6.616,-43.845) 1(-6.616,-43.819) 1(-6.616,-43.794) 1(-6.616,-43.768) 1(-6.616,-42.498) 1(-6.616,-42.219) 1(-6.591,-46.41) 1(-6.591,-45.775) 1(-6.591,-44.099) 1(-6.591,-44.073) 1(-6.591,-44.048) 1(-6.591,-44.022) 1(-6.591,-43.997) 1(-6.591,-43.972) 1(-6.591,-43.946) 1(-6.591,-43.921) 1(-6.591,-41.94) 1(-6.591,-41.609) 1(-6.566,-46.054) 1(-6.566,-45.521) 1(-6.566,-42.498) 1(-6.566,-42.244) 1(-6.54,-46.385) 1(-6.54,-45.546) 1(-6.54,-42.473) 1(-6.54,-41.965) 1(-6.515,-45.75) 1(-6.515,-45.597) 1(-6.515,-45.572) 1(-6.515,-42.448) 1(-6.515,-42.422) 1(-6.515,-42.27) 1(-6.515,-41.635) 1(-6.489,-46.029) 1(-6.489,-45.724) 1(-6.489,-45.623) 1(-6.489,-42.397) 1(-6.489,-42.295) 1(-6.489,-41.99) 1(-6.464,-46.359) 1(-6.464,-46.004) 1(-6.464,-45.699) 1(-6.464,-45.648) 1(-6.464,-42.371) 1(-6.464,-42.346) 1(-6.464,-41.66) 1(-6.439,-46.334) 1(-6.439,-45.673) 1(-6.439,-44.886) 1(-6.439,-44.861) 1(-6.439,-44.835) 1(-6.439,-44.81) 1(-6.439,-44.784) 1(-6.439,-44.759) 1(-6.439,-44.734) 1(-6.439,-44.708) 1(-6.439,-44.683) 1(-6.439,-44.657) 1(-6.439,-44.632) 1(-6.439,-44.607) 1(-6.439,-44.581) 1(-6.439,-44.556) 1(-6.439,-44.53) 1(-6.439,-44.505) 1(-6.439,-44.48) 1(-6.439,-44.454) 1(-6.439,-44.429) 1(-6.439,-44.403) 1(-6.439,-42.321) 1(-6.439,-42.016) 1(-6.413,-45.978) 1(-6.413,-41.686) 1(-6.388,-46.308) 1(-6.388,-42.041) 1(-6.362,-45.953) 1(-6.362,-42.067) 1(-6.362,-41.711) 1(-6.337,-45.927) 1(-6.312,-46.283) 1(-6.312,-42.092) 1(-6.312,-41.736) 1(-6.286,-46.258) 1(-6.286,-45.927) 1(-6.286,-42.092) 1(-6.286,-41.762) 1(-6.261,-45.953) 1(-6.261,-42.067) 1(-6.235,-46.232) 1(-6.235,-45.978) 1(-6.235,-42.041) 1(-6.21,-46.029) 1(-6.21,-46.004) 1(-6.21,-42.016) 1(-6.21,-41.99) 1(-6.21,-41.787) 1(-6.185,-46.207) 1(-6.185,-46.054) 1(-6.185,-41.965) 1(-6.185,-41.813) 1(-6.159,-46.181) 1(-6.159,-46.08) 1(-6.159,-41.94) 1(-6.159,-41.914) 1(-6.134,-46.156) 1(-6.134,-46.131) 1(-6.134,-46.105) 1(-6.134,-41.889) 1(-6.134,-41.863) 1(-6.134,-41.838) 1(-5.499,-44.378) 1(-5.499,-44.353) 1(-5.499,-44.327) 1(-5.499,-44.302) 1(-5.499,-44.276) 1(-5.499,-44.251) 1(-5.499,-44.226) 1(-5.499,-44.2) 1(-5.499,-44.175) 1(-5.499,-44.149) 1(-5.499,-44.124) 1(-5.499,-44.099) 1(-5.499,-44.073) 1(-5.499,-44.048) 1(-5.499,-44.022) 1(-5.499,-43.997) 1(-5.499,-43.972) 1(-5.499,-43.946) 1(-5.499,-43.921) 1(-5.499,-43.895) 1(-5.499,-43.87) 1(-5.499,-43.845) 1(-5.499,-43.819) 1(-5.499,-43.794) 1(-5.499,-43.768) 1(-5.499,-43.743) 1(-5.499,-43.718) 1(-5.499,-43.692) 1(-5.499,-43.667) 1(-5.499,-43.641) 1(-5.499,-43.616) 1(-5.499,-43.591) 1(-5.499,-43.565) 1(-5.499,-43.54) 1(-5.499,-43.514) 1(-5.499,-43.489) 1(-5.499,-43.464) 1(-5.499,-43.438) 1(-5.499,-43.413) 1(-5.499,-43.387) 1(-5.499,-43.362) 1(-5.499,-43.337) 1(-5.499,-43.311) 1(-5.499,-43.286) 1(-5.499,-43.26) 1(-5.499,-43.235) 1(-5.499,-43.21) 1(-5.499,-43.184) 1(-5.499,-43.159) 1(-5.499,-43.133) 1(-5.499,-43.108) 1(-5.499,-43.083) 1(-5.499,-43.057) 1(-5.499,-43.032) 1(-5.499,-43.006) 1(-5.499,-42.981) 1(-5.499,-42.956) 1(-5.499,-42.93) 1(-5.499,-42.905) 1(-5.499,-42.879) 1(-5.499,-42.854) 1(-5.499,-42.829) 1(-5.499,-42.803) 1(-5.499,-42.778) 1(-5.499,-42.752) 1(-5.499,-42.727) 1(-5.499,-42.702) 1(-5.499,-42.676) 1(-5.499,-42.651) 1(-5.499,-42.625) 1(-5.499,-42.6) 1(-5.499,-42.575) 1(-5.499,-42.549) 1(-5.499,-42.524) 1(-4.94,-42.524) 1(-4.915,-44.886) 1(-4.915,-44.861) 1(-4.915,-44.835) 1(-4.915,-44.81) 1(-4.915,-44.784) 1(-4.915,-44.759) 1(-4.915,-44.734) 1(-4.915,-44.708) 1(-4.915,-44.683) 1(-4.915,-44.657) 1(-4.915,-44.632) 1(-4.915,-44.607) 1(-4.915,-44.581) 1(-4.915,-44.556) 1(-4.915,-44.53) 1(-4.915,-44.505) 1(-4.915,-44.48) 1(-4.915,-44.454) 1(-4.915,-44.429) 1(-4.915,-44.403) 1(-4.915,-44.378) 1(-4.915,-44.353) 1(-4.915,-44.327) 1(-4.915,-44.302) 1(-4.915,-44.276) 1(-4.915,-44.251) 1(-4.915,-44.226) 1(-4.915,-44.2) 1(-4.915,-44.175) 1(-4.915,-44.149) 1(-4.915,-44.124) 1(-4.915,-44.099) 1(-4.915,-44.073) 1(-4.915,-44.048) 1(-4.915,-44.022) 1(-4.915,-43.997) 1(-4.915,-43.972) 1(-4.915,-43.946) 1(-4.915,-43.921) 1(-4.915,-43.895) 1(-4.915,-43.87) 1(-4.915,-43.845) 1(-4.915,-43.819) 1(-4.915,-43.794) 1(-4.915,-43.768) 1(-4.915,-43.743) 1(-4.915,-43.718) 1(-4.915,-43.692) 1(-4.915,-43.667) 1(-4.915,-43.641) 1(-4.915,-43.616) 1(-4.915,-43.591) 1(-4.915,-43.565) 1(-4.915,-43.54) 1(-4.915,-43.514) 1(-4.915,-43.489) 1(-4.915,-43.464) 1(-4.915,-43.438) 1(-4.915,-43.413) 1(-4.915,-43.387) 1(-4.915,-43.362) 1(-4.915,-43.337) 1(-4.915,-43.311) 1(-4.915,-43.286) 1(-4.915,-43.26) 1(-4.915,-43.235) 1(-4.915,-43.21) 1(-4.915,-43.184) 1(-4.915,-43.159) 1(-4.915,-43.133) 1(-4.915,-43.108) 1(-4.915,-43.083) 1(-4.915,-43.057) 1(-4.915,-43.032) 1(-4.915,-43.006) 1(-4.915,-42.981) 1(-4.915,-42.956) 1(-4.915,-42.93) 1(-4.915,-42.905) 1(-4.915,-42.879) 1(-4.915,-42.854) 1(-4.915,-42.829) 1(-4.915,-42.803) 1(-4.915,-42.778) 1(-4.915,-42.752) 1(-4.915,-42.727) 1(-4.915,-42.702) 1(-4.915,-42.676) 1(-4.915,-42.651) 1(-4.915,-42.625) 1(-4.915,-42.6) 1(-4.915,-42.575) 1(-4.915,-42.549)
